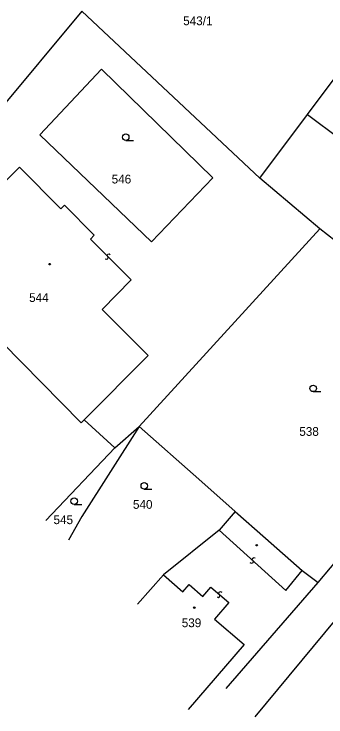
# Model space of a CAD drawing. Extents: x -748509 to -748117, y -967868 to -967533.
# Drawn here: x -748249.3 to -748213.7, y -967741.5 to -967661.4 of the extents above; entities that cross this region are included whole.
import ezdxf

# ---------------------------------------------------------------- set-up
doc = ezdxf.new("R2010")
doc.units = 0
doc.layers.add('KM', color=7, linetype='Continuous')
doc.layers.add('Vnitřní kresba', color=7, linetype='Continuous')

msp = doc.modelspace()

# ---------------------------------------------------------------- linework, layer by layer
at = {"layer": 'KM'}
for p, q in [((-748241.55, -967661.04), (-748256.12, -967678.46)), ((-748241.55, -967661.04), (-748221.23, -967680.08)), ((-748236.557, -967675.78), (-748235.682, -967675.78)), ((-748214.39, -967685.86), (-748221.23, -967680.08)), ((-748214.39, -967685.86), (-748235.02, -967708.41)), ((-748208.71, -967690.36), (-748214.39, -967685.86)), ((-748214.57, -967726.18), (-748195.27, -967703.22)), ((-748215.157, -967704.43), (-748214.282, -967704.43)), ((-748237.79, -967710.82), (-748235.02, -967708.41)), ((-748237.79, -967710.82), (-748245.69, -967719.128)), ((-748234.432, -967715.539), (-748233.557, -967715.539)), ((-748242.449, -967717.285), (-748241.574, -967717.285)), ((-748225.066, -967738.289), (-748214.57, -967726.18))]:
    msp.add_line(p, q, dxfattribs=at)
for points in [[(-748221.23, -967680.08), (-748215.8, -967672.81), (-748209.78, -967664.8), (-748208.42, -967663.17)], [(-748233.62, -967687.33), (-748246.37, -967675.14), (-748239.34, -967667.67), (-748226.6, -967680.05), (-748233.62, -967687.33)], [(-748256.12, -967678.46), (-748252.29, -967682.37), (-748259.73, -967689.65), (-748241.64, -967707.97), (-748241.3, -967707.63), (-748237.79, -967710.82)], [(-748235.02, -967708.41), (-748241.56, -967718.67), (-748243.104, -967721.35)], [(-748235.02, -967708.41), (-748228.22, -967714.4), (-748224.05, -967718.08)], [(-748224.05, -967718.08), (-748225.87, -967720.23), (-748232.24, -967725.33), (-748235.209, -967728.671)], [(-748224.05, -967718.08), (-748220.6, -967721.12), (-748216.39, -967724.84), (-748214.57, -967726.18)], [(-748212.57, -967730.39), (-748221.81, -967741.523)]]:
    msp.add_lwpolyline(points, dxfattribs=at)
for centre, radius in [((-748236.556, -967675.405), 0.375), ((-748245.253, -967689.89), 0.0875), ((-748215.156, -967704.055), 0.375), ((-748234.432, -967715.164), 0.375), ((-748242.448, -967716.91), 0.375), ((-748221.593, -967721.94), 0.0875), ((-748228.721, -967729.061), 0.0875)]:
    msp.add_circle(centre, radius, dxfattribs=at)
at = {"layer": 'Vnitřní kresba'}
for p, q in [((-748215.8, -967672.81), (-748212.03, -967675.63)), ((-748252.29, -967682.37), (-748248.67, -967678.82)), ((-748248.67, -967678.82), (-748243.95, -967683.58)), ((-748243.95, -967683.58), (-748243.53, -967683.17)), ((-748243.53, -967683.17), (-748240.14, -967686.58)), ((-748240.14, -967686.58), (-748240.59, -967687.04)), ((-748240.59, -967687.04), (-748235.92, -967691.69)), ((-748235.92, -967691.69), (-748239.26, -967695.05)), ((-748239.26, -967695.05), (-748233.99, -967700.3)), ((-748233.99, -967700.3), (-748241.3, -967707.63)), ((-748225.87, -967720.23), (-748218.26, -967727.12)), ((-748232.24, -967725.33), (-748230.03, -967727.24)), ((-748218.26, -967727.12), (-748216.39, -967724.84)), ((-748230.03, -967727.24), (-748229.32, -967726.42)), ((-748229.32, -967726.42), (-748227.75, -967727.78)), ((-748227.75, -967727.78), (-748226.83, -967726.71)), ((-748226.83, -967726.71), (-748224.79, -967728.48)), ((-748224.79, -967728.48), (-748226.41, -967730.36)), ((-748226.41, -967730.36), (-748223.03, -967733.28)), ((-748223.03, -967733.28), (-748229.41, -967740.67))]:
    msp.add_line(p, q, dxfattribs=at)
for points in [[(-748238.884, -967689.268), (-748238.743, -967689.339), (-748238.591, -967689.271), (-748238.545, -967689.126), (-748238.655, -967688.896), (-748238.599, -967688.755), (-748238.447, -967688.701), (-748238.32, -967688.772)], [(-748221.782, -967723.426), (-748221.927, -967723.362), (-748222.075, -967723.437), (-748222.114, -967723.584), (-748221.993, -967723.808), (-748222.042, -967723.952), (-748222.192, -967724.013), (-748222.322, -967723.948)], [(-748226.117, -967727.826), (-748225.971, -967727.886), (-748225.824, -967727.809), (-748225.788, -967727.661), (-748225.914, -967727.439), (-748225.867, -967727.294), (-748225.719, -967727.231), (-748225.587, -967727.292)]]:
    msp.add_lwpolyline(points, dxfattribs=at)

# ---------------------------------------------------------------- texts
at = {"layer": 'KM'}
for s, p in [('543/1', (-748229.99, -967662.64)), ('546', (-748238.161, -967680.69)), ('544', (-748247.59, -967694.2)), ('538', (-748216.727, -967709.47)), ('540', (-748235.728, -967717.787)), ('545', (-748244.801, -967719.535)), ('539', (-748230.157, -967731.287))]:
    msp.add_text(s, height=1, dxfattribs=at).set_placement(p)

doc.saveas('drawing.dxf')
